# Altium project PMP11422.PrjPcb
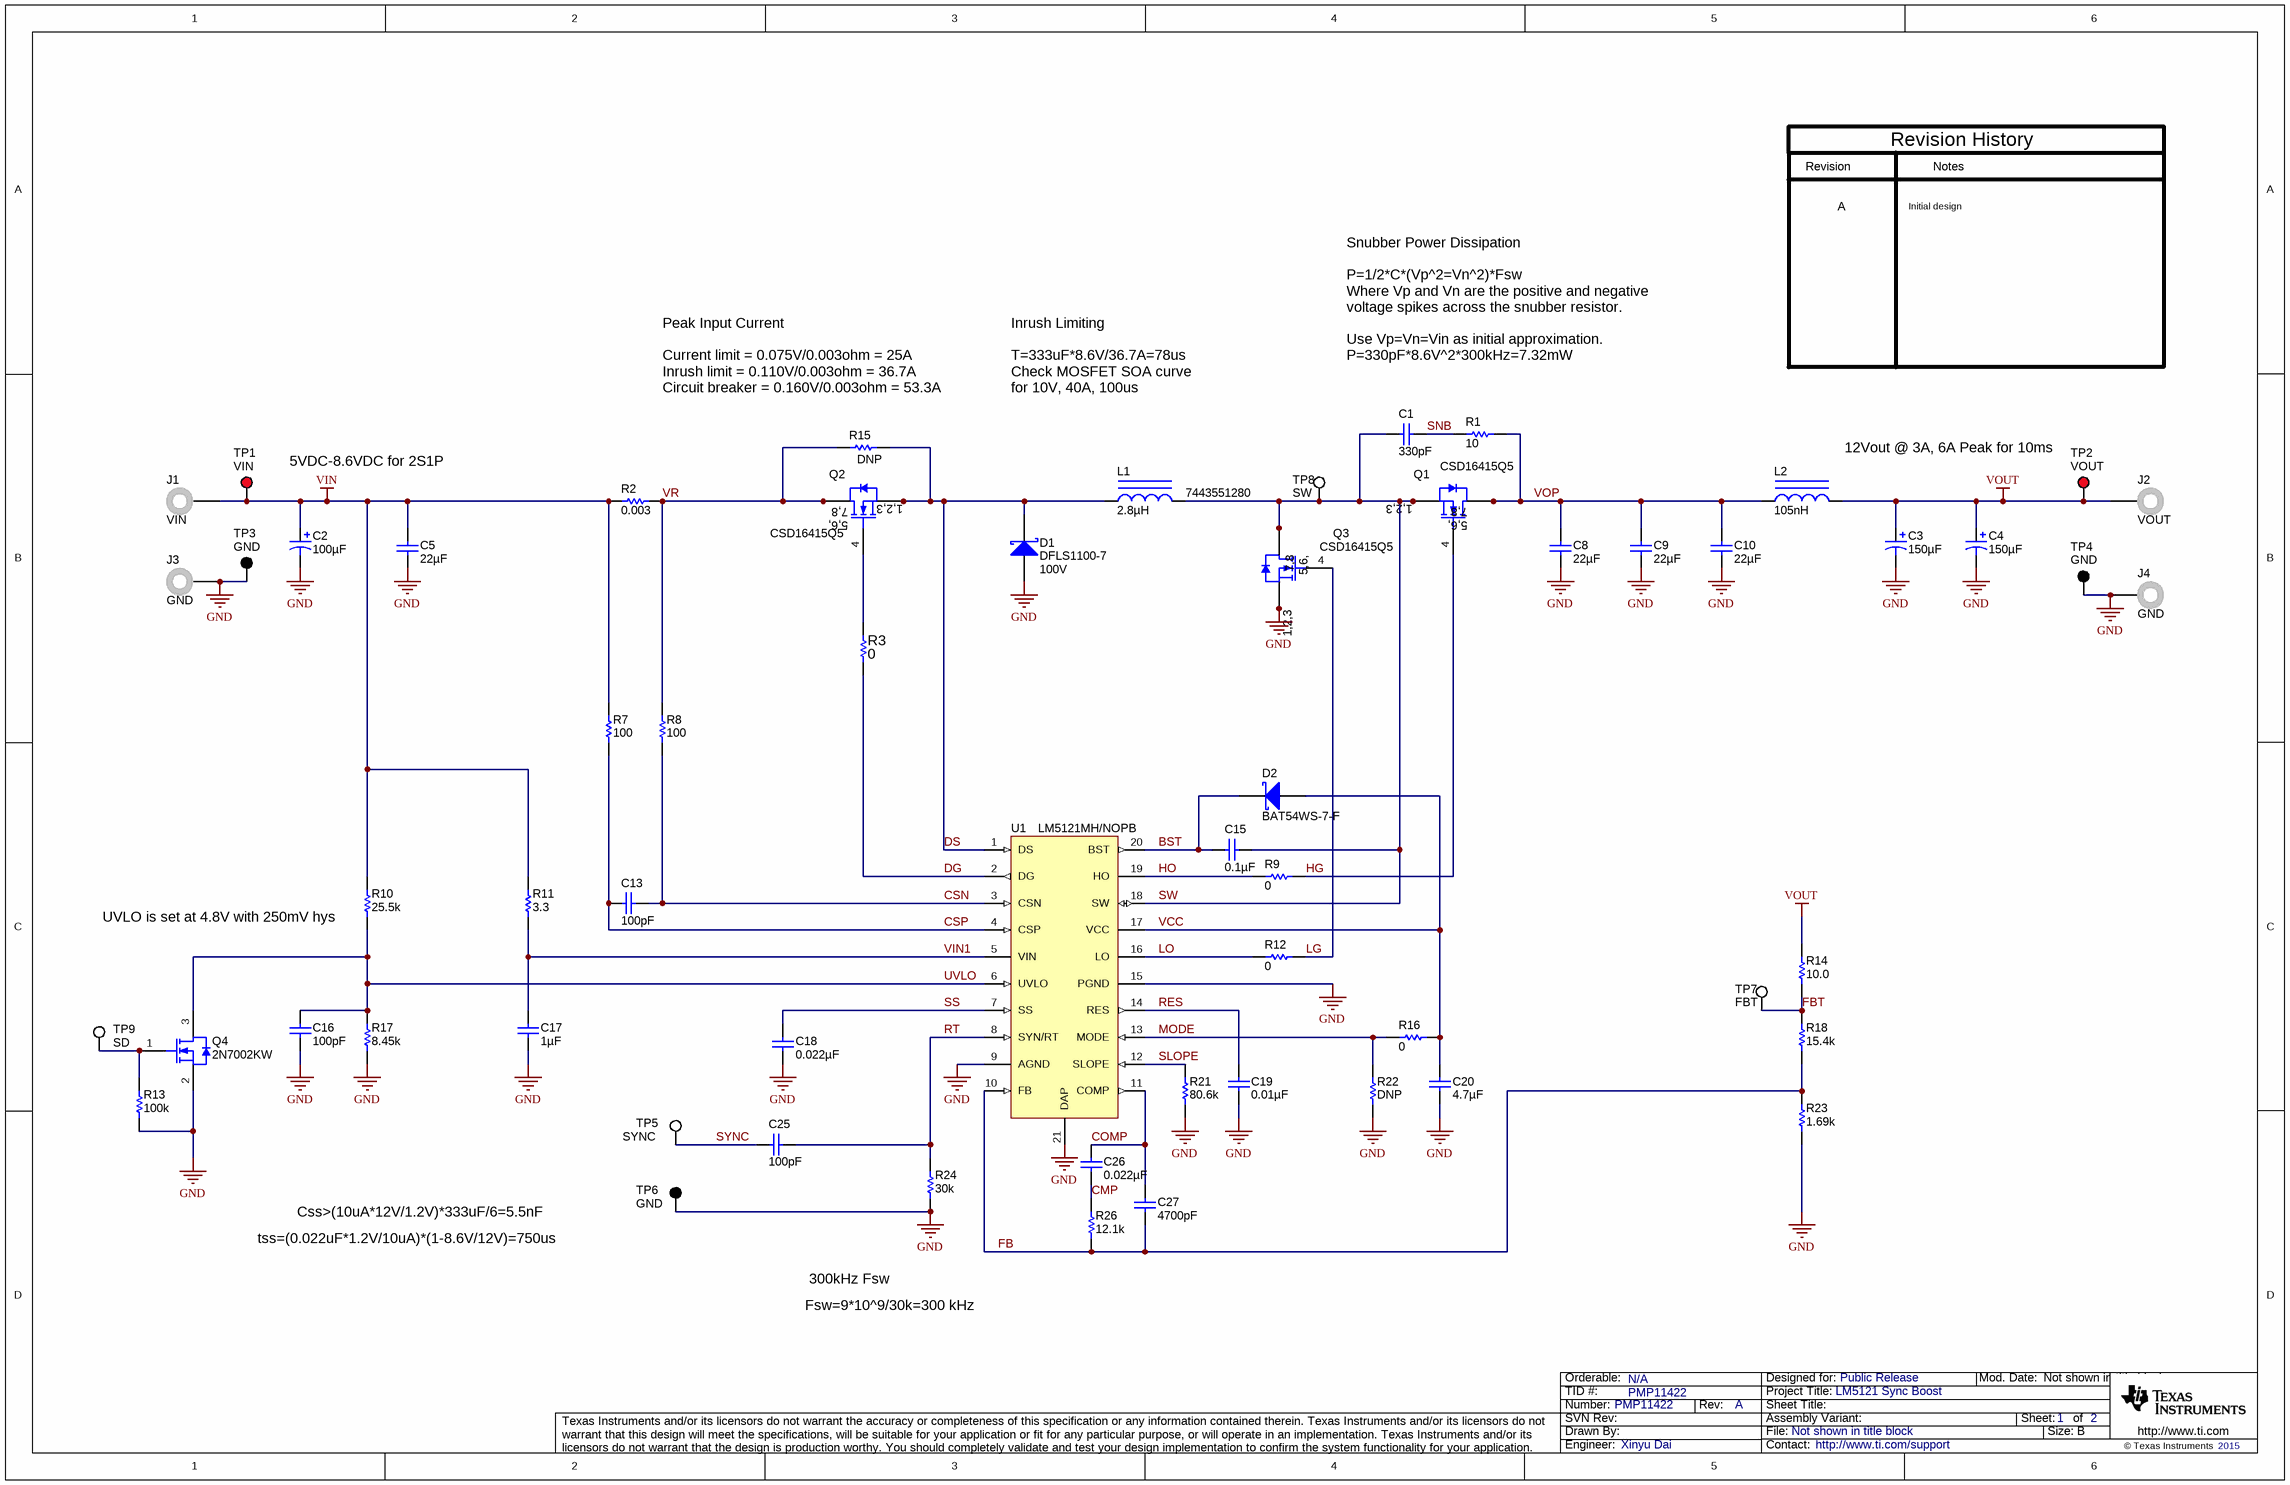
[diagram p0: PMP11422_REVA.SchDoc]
CopyrightYear: 2015; EVM_Orderable: N/A; PCB_Layout: Xinyu Dai; PCB_Rev: A; PRJ_Customer: Public Release; PRJ_Engineer: Xinyu Dai; PRJ_Number: PMP11422; PRJ_Title: LM5121 Sync Boost; SCH_Rev: A; TechSupport: http://www.ti.com/support; TID: PMP11422
2 sheets, 67 parts. Net scope: global (net labels, ports and power ports of the same name join across sheets).
Board file: PMP11422_REVA.PcbDoc
Sheets:
  PMP11422_REVA.SchDoc
  PMP11422_REVA_Hardware.SchDoc

## Sheet PMP11422_REVA.SchDoc
size 431 x 279 mm; Date: Not shown in title block; ApprovedBy: Not shown in title block; CheckedBy: Not shown in title block; Author: Not shown in title block; CompanyName: Not shown in title block; Engineer: Not shown in title block; Organization: Not shown in title block; Address1: Not shown in title block; Address2: Not shown in title block; Address3: Not shown in title block; Address4: Not shown in title block; DocumentNumber: 1; Revision: Use project parameter SCH_Rev; SheetNumber: 1; SheetTotal: 2; PageSetup: Record=PageOptions¦CenterHorizontal=True¦CenterVertical=True¦PrintScale=1.00¦XCorrection=1.00¦YCorrection=1.00¦PrintKind=0¦BorderSize=5000000¦LeftOffset=0¦BottomOffset=0¦Orientation=2¦PaperLength=1000¦PaperWidth=1000¦Scale=100¦PaperSource=15¦PrintQuality=600¦MediaType=1¦DitherType=10¦PaperKind=Letter¦PrintScaleMode=1

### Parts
C1  ValueDisplayed: 330pF  [0603]  (hidden comment: GRM188R72A331KA01D)
C2  ValueDisplayed: 100µF  [SM_RADIAL_D]  (hidden comment: EEE-FK1C101P)
C3  ValueDisplayed: 150µF  [MZJ_F80]  (hidden comment: EMZJ160ADA151MF80G)
C4  ValueDisplayed: 150µF  [MZJ_F80]  (hidden comment: EMZJ160ADA151MF80G)
C5  ValueDisplayed: 22µF  [1210]  (hidden comment: GRM32ER71E226KE15L)
C8  ValueDisplayed: 22µF  [1210]  (hidden comment: GRM32ER71E226KE15L)
C9  ValueDisplayed: 22µF  [1210]  (hidden comment: GRM32ER71E226KE15L)
C10  ValueDisplayed: 22µF  [1210]  (hidden comment: GRM32ER71E226KE15L)
C13  ValueDisplayed: 100pF  [0402]  (hidden comment: GRM1555C1H101JA01D)
C15  ValueDisplayed: 0.1µF  [0402]  (hidden comment: GRM155R71C104KA88D)
C16  ValueDisplayed: 100pF  [0402]  (hidden comment: GRM1555C1H101JA01D)
C17  ValueDisplayed: 1µF  [0603]  (hidden comment: GRM188R71C105KA12D)
C18  ValueDisplayed: 0.022µF  [0402]  (hidden comment: GCM155R71H223KA55D)
C19  ValueDisplayed: 0.01µF  [0402]  (hidden comment: GCM155R71H103KA55D)
C20  ValueDisplayed: 4.7µF  [0603]  (hidden comment: GRM188R61C475KAAJ)
C25  ValueDisplayed: 100pF  [0402]  (hidden comment: GRM1555C1H101JA01D)
C26  ValueDisplayed: 0.022µF  [0402]  (hidden comment: GCM155R71H223KA55D)
C27  ValueDisplayed: 4700pF  [0402]  (hidden comment: GRM155R71H472KA01D)
D1  DFLS1100-7  value 100V  [powerDI123]
D2  BAT54WS-7-F  [sod-323]
J1  VIN  [Keystone575-8]
J2  VOUT  [Keystone575-8]
J3  GND  [Keystone575-8]
J4  GND  [Keystone575-8]
L1  7443551280  ValueDisplayed: 2.8µH  [WE-HCA1]
L2  ValueDisplayed: 105nH  [WE-HCM_7050]  (hidden comment: 744302010)
Q1  CSD16415Q5  [TRANS_NexFET_Q5]
Q2  CSD16415Q5  [TRANS_NexFET_Q5]
Q3  CSD16415Q5  [TRANS_NexFET_Q5]
Q4  2N7002KW  [SOT-323]
R1  value 10  [1206]  (hidden comment: CRCW120610R0JNEA)
R2  ValueDisplayed: 0.003  [2512]  (hidden comment: ERJ-M1WSF3M0U)
R3  value 0  [0402]  (hidden comment: CRCW04020000Z0ED)
R7  ValueDisplayed: 100  [0402]  (hidden comment: CRCW0402100RJNED)
R8  ValueDisplayed: 100  [0402]  (hidden comment: CRCW0402100RJNED)
R9  value 0  [0402]  (hidden comment: CRCW04020000Z0ED)
R10  ValueDisplayed: 25.5k  [0402]  (hidden comment: CRCW040225K5FKED)
R11  value 3.3  [0402]  (hidden comment: CRCW04023R30JNED)
R12  value 0  [0402]  (hidden comment: CRCW04020000Z0ED)
R13  ValueDisplayed: 100k  [0402]  (hidden comment: CRCW0402100KJNED)
R14  value 10.0  [0402]  (hidden comment: CRCW040210R0FKED)
R15  DNP  [2512]
R16  value 0  [0402]  (hidden comment: CRCW04020000Z0ED)
R17  ValueDisplayed: 8.45k  [0402]  (hidden comment: CRCW04028K45FKED)
R18  ValueDisplayed: 15.4k  [0402]  (hidden comment: CRCW040215K4FKED)
R21  ValueDisplayed: 80.6k  [0402]  (hidden comment: CRCW040280K6FKED)
R22  value DNP  [0402]  (hidden comment: DNP1)
R23  value 1.69k  [0402]  (hidden comment: CRCW04021K69FKED)
R24  ValueDisplayed: 30k  [0402]  (hidden comment: CRCW040230K0JNED)
R26  ValueDisplayed: 12.1k  [0402]  (hidden comment: CRCW040212K1FKED)
TP1  VIN  [Keystone5010]
TP2  VOUT  [Keystone5010]
TP3  GND  [Keystone5011]
TP4  GND  [Keystone5011]
TP5  SYNC  [Keystone5012]
TP6  GND  [Keystone5011]
TP7  FBT  [Keystone5012]
TP8  SW  [Keystone5012]
TP9  SD  [Keystone5012]
U1  LM5121MH/NOPB  [PWP0020A_N]

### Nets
GND: C2.2(-) C3.2(-) C4.2(-) C5.2 C8.2 C9.2 C10.2 C16.2 C17.2 C18.2 C19.2 C20.2 D1.2(A) J3.1 J4.1 Q3.1(S) Q3.2(S) Q3.3(S) Q4.2(S) R13.1 R17.1 R21.1 R22.1 R23.1 R24.1 TP3.1 TP4.1 TP6.1 U1.9(AGND) U1.15(PGND) U1.21(DAP)
VIN: C2.1(+) C5.1 J1.1 R2.1 R7.2 R10.2 R11.2 TP1.1
VOUT: C3.1(+) C4.1(+) J2.1 L2.2 R14.2 TP2.1
BST: C15.1 D2.1(K) U1.20(BST)
CMP: C26.2 R26.2
COMP: C26.1 C27.2 U1.11(COMP)
CSN: C13.1 R8.1 U1.3(CSN)
CSP: C13.2 R7.1 U1.4(CSP)
DG: R3.2 U1.2(DG)
DS: D1.1(K) L1.1 Q2.1(S) Q2.2(S) Q2.3(S) R15.2 U1.1(DS)
FB: C27.1 R18.1 R23.2 R26.1 U1.10(FB)
FBT: R14.1 R18.2 TP7.1
HG: Q1.4(G) R9.2
HO: R9.1 U1.19(HO)
LG: Q3.4(G) R12.2
LO: R12.1 U1.16(LO)
MODE: R16.2 R22.2 U1.13(MODE)
RES: C19.1 U1.14(RES)
RT: C25.1 R24.2 U1.8(SYN/RT)
SLOPE: R21.2 U1.12(SLOPE)
SNB: C1.1 R1.1
SS: C18.1 U1.7(SS)
SW: C1.2 C15.2 L1.2 Q1.1(S) Q1.2(S) Q1.3(S) Q3.5(D) Q3.6(D) Q3.7(D) Q3.8(D) Q3.9(D) TP8.1 U1.18(SW)
SYNC: C25.2 TP5.1
UVLO: C16.1 Q4.3(D) R10.1 R17.2 U1.6(UVLO)
VCC: C20.1 D2.2(A) R16.1 U1.17(VCC)
VIN1: C17.1 R11.1 U1.5(VIN)
VOP: C8.1 C9.1 C10.1 L2.1 Q1.5(D) Q1.6(D) Q1.7(D) Q1.8(D) Q1.9(D) R1.2
VR: Q2.5(D) Q2.6(D) Q2.7(D) Q2.8(D) Q2.9(D) R2.2 R8.2 R15.1
NetQ2_4: Q2.4(G) R3.1
NetQ4_1: Q4.1(G) R13.2 TP9.1

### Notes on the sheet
- Revision
- Notes
- Revision History
- A
- Initial design
- Snubber Power Dissipation
  P=1/2*C*(Vp^2=Vn^2)*Fsw
  Where Vp and Vn are the positive and negative voltage spikes across the snubber resistor.
  Use Vp=Vn=Vin as initial approximation.
  P=330pF*8.6V^2*300kHz=7.32mW
- (near R15) Peak Input Current
  Current limit = 0.075V/0.003ohm = 25A
  Inrush limit = 0.110V/0.003ohm = 36.7A
  Circuit breaker = 0.160V/0.003ohm = 53.3A
- Inrush Limiting
  T=333uF*8.6V/36.7A=78us
  Check MOSFET SOA curve
  for 10V, 40A, 100us
- 5VDC-8.6VDC for 2S1P
- 12Vout @ 3A, 6A Peak for 10ms
- (near R10) UVLO is set at 4.8V with 250mV hys
- tss=(0.022uF*1.2V/10uA)*(1-8.6V/12V)=750us
- Css>(10uA*12V/1.2V)*333uF/6=5.5nF
- 300kHz Fsw
- Fsw=9*10^9/30k=300 kHz

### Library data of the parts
C1 = GRM188R72A331KA01D: CAP, CERM, 330pF, 100V, +/-10%, X7R, 0603; Manufacturer: MuRata; Polarized: N; CompType: Capacitor; U/M: EA; Cap_F: 0.00000000033; Tolerance_%: 10; Value1: Unknown; VDC_V: 100; TaMin_C: -55; TaMax_C: 125
C2 = EEE-FK1C101P: CAP, AL, 100 µF, 16 V, +/- 20%, 0.36 ohm, SMD; Manufacturer: Panasonic; Polarized: Y; CompType: Capacitor; Value: 100uF; U/M: EA; Cap_F: 0.0001; Tolerance_%: 20; VDC_V: 16; Value2: 16V; ESR_ohm: 0.36; IRMS_A: 0.24; TaMin_C: -55; TaMax_C: 105; Cap_Case: D; AEC Category: Q200
C3 C4 = EMZJ160ADA151MF80G: CAP, AL, 150 µF, 16 V, +/- 20%, 0.16 ohm, SMD; Manufacturer: Chemi-Con; Polarized: Y; CompType: Capacitor; Value: 150uF; U/M: EA; Cap_F: 0.00015; Tolerance_%: 20; VDC_V: 16; Value2: 16V; ESR_ohm: 0.16; IRMS_A: 0.6; TaMin_C: -55; TaMax_C: 105; Cap_Case: 6.3x7.7mm; AEC Category: Q200; AEC Qualified: N
C5 = GRM32ER71E226KE15L: CAP, CERM, 22 µF, 25 V, +/- 10%, X7R, 1210; Manufacturer: MuRata; Polarized: N; CompType: Capacitor; Value: 22uF; U/M: EA; Cap_F: 0.000022; Tolerance_%: 10; Value1: Unknown; VDC_V: 25; TaMin_C: -55; TaMax_C: 125; Value2: 25V; AEC Category: Q200
C8-C10 = GRM32ER71E226KE15L: CAP, CERM, 22 µF, 25 V, +/- 10%, X7R, 1210; Manufacturer: MuRata; Polarized: N; CompType: Capacitor; Value: 22uF; U/M: EA; Cap_F: 0.000022; Tolerance_%: 10; Value1: Unknown; VDC_V: 25; Value2: 25V; TaMin_C: -55; TaMax_C: 125; AEC Category: Q200
C13 = GRM1555C1H101JA01D: CAP, CERM, 100pF, 50V, +/-5%, C0G/NP0, 0402; Manufacturer: MuRata; Polarized: N; CompType: Capacitor; U/M: EA; Cap_F: 0.0000000001; Tolerance_%: 5; Value1: Unknown; VDC_V: 50; TaMin_C: -55; TaMax_C: 125
C15 = GRM155R71C104KA88D: CAP, CERM, 0.1uF, 16V, +/-10%, X7R, 0402; Manufacturer: MuRata; Polarized: N; CompType: Capacitor; U/M: EA; Cap_F: 0.0000001; Tolerance_%: 10; Value1: Unknown; VDC_V: 16; TaMin_C: -55; TaMax_C: 125
C16 C25 = GRM1555C1H101JA01D: CAP, CERM, 100 pF, 50 V, +/- 5%, C0G/NP0, 0402; Manufacturer: MuRata; Polarized: N; CompType: Capacitor; Value: 100pF; U/M: EA; Cap_F: 0.0000000001; Tolerance_%: 5; Value1: Unknown; VDC_V: 50; Value2: 50V; TaMin_C: -55; TaMax_C: 125; AEC Category: Q200
C17 = GRM188R71C105KA12D: CAP, CERM, 1 µF, 16 V, +/- 10%, X7R, 0603; Manufacturer: MuRata; Polarized: N; CompType: Capacitor; Value: 1uF; U/M: EA; Cap_F: 0.000001; Tolerance_%: 10; ESR_ohm: 0.011; Value1: 0.011 ohm; VDC_V: 16; Value2: 16V; TaMin_C: -55; TaMax_C: 125; AEC Category: Q200
C18 C26 = GCM155R71H223KA55D: CAP, CERM, 0.022 µF, 50 V, +/- 10%, C0G/NP0, 0402; Manufacturer: MuRata; Polarized: N; CompType: Capacitor; Value: 0.022uF; U/M: EA; Cap_F: 0.000000022; Tolerance_%: 10; Value1: Unknown; VDC_V: 50; Value2: 50V; TaMin_C: -55; TaMax_C: 125; AEC Category: Q200
C19 = GCM155R71H103KA55D: CAP, CERM, 0.01 µF, 50 V, +/- 10%, C0G/NP0, 0402; Manufacturer: MuRata; Polarized: N; CompType: Capacitor; Value: 0.01uF; U/M: EA; Cap_F: 0.00000001; Tolerance_%: 10; Value1: Unknown; VDC_V: 50; Value2: 50V; TaMin_C: -55; TaMax_C: 125; AEC Category: Q200
C20 = GRM188R61C475KAAJ: CAP, CERM, 4.7 µF, 16 V, +/- 10%, X5R, 0603; Manufacturer: MuRata; Polarized: N; CompType: Capacitor; Value: 4.7uF; U/M: EA; Cap_F: 0.0000047; Tolerance_%: 10; Value1: Unknown; VDC_V: 16; Value2: 16V; TaMin_C: -55; TaMax_C: 85; AEC Category: Q200
C27 = GRM155R71H472KA01D: CAP, CERM, 4700 pF, 50 V, +/- 10%, X7R, 0402; Manufacturer: MuRata; Polarized: N; CompType: Capacitor; Value: 4700pF; U/M: EA; Cap_F: 0.0000000047; Tolerance_%: 10; Value1: Unknown; VDC_V: 50; Value2: 50V; TaMin_C: -55; TaMax_C: 125; AEC Category: Q200
D1 = DFLS1100-7: Diode, Schottky, 100V, 1A, PowerDI123; Manufacturer: Diodes Inc.; U/M: EA; Vf_V: 0.77; Value2: 0.77V; Io_A: 1; Vr_V: 100; TJmax_C: 175; RJC_CperW: 7
D2 = BAT54WS-7-F: Diode, Schottky, 30 V, 0.2 A, SOD-323; Manufacturer: Diodes Inc.; Value: 30V; U/M: EA; Vf_V: 0.7; Value1: 0.2A; Value2: 0.7V; Io_A: 0.2; Vr_V: 30; TJmax_C: 125; AEC Category: Q101
J1-J4 = 575-8: Standard Banana Jack, Uninsulated, 8.9mm; Manufacturer: Keystone; CompType: Connector; U/M: EA
L1 = 7443551280: Inductor, Shielded Drum Core, WE-Perm, 2.8 µH, 17.5 A, 0.0033 ohm, SMD; Manufacturer: Wurth Elektronik; Value: 2.8uH; Ind_H: 2.8E-6; Imax_A: 17.5; Irms: 20A @ 50C rise; Isat: 17.5A @ 30% inductance drop; DCR_ohm: 0.0033; Value2: 17.5A; AEC Category: Q200
L2 = 744302010: Inductor, Shielded Drum Core, Ferrite, 105 nH, 30 A, 0.000235 ohm, SMD; Manufacturer: Wurth Elektronik; Value: 105nH; Ind_H: 105.0E-9; Imax_A: 30; Irms: 30A @ 50C rise; Isat: 45A @ 20% inductance drop; Value2: 30A; AEC Category: Q200
Q1 Q3 = CSD16415Q5: MOSFET, N-CH, 25 V, 100 A, SON 5x6mm; Manufacturer: Texas Instruments; Alternate Manufacturer: None; Value: 25V; U/M: EA; ChType: N; VdsMax_V: 25; Value1: 0.0015 ohm; Rdson45_ohm: 0.0015; Value2: 21 nC; QgTyp_nC: 21; Vgs_V: 16; IdsMax_A: 100; AEC Category: Q101
Q2 = CSD16415q5: MOSFET, N-CH, 25 V, 100 A, SON 5x6mm; Manufacturer: Texas Instruments; Alternate Manufacturer: None; Value: 25V; U/M: EA; ChType: N; VdsMax_V: 25; Value1: 0.0015 ohm; Rdson45_ohm: 0.0015; Value2: 21 nC; QgTyp_nC: 21; Vgs_V: 16; IdsMax_A: 100; AEC Category: Q101
Q4 = 2N7002KW: MOSFET, N-CH, 60 V, 0.31 A, SOT-323; Manufacturer: Fairchild Semiconductor; Alternate Manufacturer: None; U/M: EA; ChType: N; Value: 60V; VdsMax_V: 60; Value1: 1.6 ohm; Rdson45_ohm: 1.6; Value2: ? nC; Vgs_V: 2.1; IdsMax_A: 0.31; AEC Category: Q101
R1 = CRCW120610R0JNEA: RES, 10 ohm, 5%, 0.25W, 1206; Manufacturer: Vishay-Dale; CompType: Resistor; Value_Code: 10R0; Tolerance_%: 5; Power_W: 0.25; VDC_V: 200; TempCo: 200 ppm/C; EIA_Code: E24; U/M: EA
R2 = ERJ-M1WSF3M0U: RES, 0.003, 1%, 1 W, 2512; Manufacturer: Panasonic; CompType: Resistor; Value: 0.003; Value_Code: 3L000; Tolerance_%: 1; Value2: 1W; TempCo: 350 ppm/C; EIA_Code: E96; U/M: EA; AEC Category: Q200
R3 = CRCW04020000Z0ED: RES, 0 ohm, 5%, 0.063W, 0402; Manufacturer: Vishay-Dale; CompType: Resistor; U/M: EA; Value_Code: 0000; Tolerance_%: 5; Power_W: 0.063; VDC_V: 50; TempCo: 200 ppm/C; EIA_Code: E24
R7 R8 = CRCW0402100RJNED: RES, 100, 5%, 0.063 W, 0402; Manufacturer: Vishay-Dale; CompType: Resistor; Value: 100; Value_Code: 100R; Tolerance_%: 5; Power_W: 0.063; Value2: 0.063W; VDC_V: 50; TempCo: 200 ppm/C; EIA_Code: E24; U/M: EA; AEC Category: Q200
R9 R12 R16 = CRCW04020000Z0ED: RES, 0 ohm, 5%, 0.063W, 0402; Manufacturer: Vishay-Dale; CompType: Resistor; Value_Code: 0000; Tolerance_%: 5; Power_W: 0.063; VDC_V: 50; TempCo: 200 ppm/C; EIA_Code: E24; U/M: EA
R10 = CRCW040225K5FKED: RES, 25.5 k, 1%, 0.063 W, 0402; Manufacturer: Vishay-Dale; CompType: Resistor; Value: 25.5k; Res_ohm: 25500; Value_Code: 25k5; Tolerance_%: 1; Power_W: 0.063; Value2: 0.063W; VDC_V: 50; TempCo: 100 ppm/C; EIA_Code: E96; U/M: EA; AEC Category: Q200
R11 = CRCW04023R30JNED: RES, 3.3 ohm, 5%, 0.063W, 0402; Manufacturer: Vishay-Dale; CompType: Resistor; Value_Code: 3R30; Tolerance_%: 5; Power_W: 0.063; VDC_V: 50; TempCo: 200 ppm/C; EIA_Code: E24; U/M: EA
R13 = CRCW0402100KJNED: RES, 100 k, 5%, 0.063 W, 0402; Manufacturer: Vishay-Dale; CompType: Resistor; Value: 100k; Res_ohm: 100000; Tolerance_%: 5; Power_W: 0.063; Value2: 0.063W; VDC_V: 50; TempCo: 200 ppm/C; EIA_Code: E24; U/M: EA; AEC Category: Q200
R14 = CRCW040210R0FKED: RES, 10.0 ohm, 1%, 0.063W, 0402; Manufacturer: Vishay-Dale; CompType: Resistor; Res_ohm: 10; Value_Code: 10R0; Tolerance_%: 1; Power_W: 0.063; VDC_V: 50; TempCo: 100 ppm/C; EIA_Code: E96; U/M: EA
R15 = ERJ-M1WTF1M0U: RES, 0.001, 1%, 1 W, 2512; Manufacturer: Panasonic; CompType: Resistor; Value: 0.001; Value_Code: 1L000; Tolerance_%: 1; Value2: 1W; TempCo: ppm/C; EIA_Code: E96; U/M: EA; AEC Category: Q200
R17 = CRCW04028K45FKED: RES, 8.45 k, 1%, 0.063 W, 0402; Manufacturer: Vishay-Dale; CompType: Resistor; Value: 8.45k; Res_ohm: 8450; Value_Code: 8k45; Tolerance_%: 1; Power_W: 0.063; Value2: 0.063W; VDC_V: 50; TempCo: 100 ppm/C; EIA_Code: E96; U/M: EA; AEC Category: Q200
R18 = CRCW040215K4FKED: RES, 15.4 k, 1%, 0.063 W, 0402; Manufacturer: Vishay-Dale; CompType: Resistor; Value: 15.4k; Res_ohm: 15400; Value_Code: 15k4; Tolerance_%: 1; Power_W: 0.063; Value2: 0.063W; VDC_V: 50; TempCo: 100 ppm/C; EIA_Code: E96; U/M: EA; AEC Category: Q200
R21 = CRCW040280K6FKED: RES, 80.6 k, 1%, 0.063 W, 0402; Manufacturer: Vishay-Dale; CompType: Resistor; Value: 80.6k; Res_ohm: 80600; Value_Code: 80k6; Tolerance_%: 1; Power_W: 0.063; Value2: 0.063W; VDC_V: 50; TempCo: 100 ppm/C; EIA_Code: E96; U/M: EA; AEC Category: Q200
R22 = Resistor: RES, xxx ohm, x%, xW, [PackageReference]; Manufacturer: Used in BOM report; U/M: EA
R23 = CRCW04021K69FKED: RES, 1.69k ohm, 1%, 0.063W, 0402; Manufacturer: Vishay-Dale; CompType: Resistor; Res_ohm: 1690; Value_Code: 1k69; Tolerance_%: 1; Power_W: 0.063; VDC_V: 50; TempCo: 100 ppm/C; EIA_Code: E96; U/M: EA
R24 = CRCW040230K0JNED: RES, 30 k, 5%, 0.063 W, 0402; Manufacturer: Vishay-Dale; CompType: Resistor; Value: 30k; Res_ohm: 30000; Value_Code: 30k0; Tolerance_%: 5; Power_W: 0.063; Value2: 0.063W; VDC_V: 50; TempCo: 200 ppm/C; EIA_Code: E24; U/M: EA; AEC Category: Q200
R26 = CRCW040212K1FKED: RES, 12.1 k, 1%, 0.063 W, 0402; Manufacturer: Vishay-Dale; CompType: Resistor; Value: 12.1k; Res_ohm: 12100; Value_Code: 12k1; Tolerance_%: 1; Power_W: 0.063; Value2: 0.063W; VDC_V: 50; TempCo: 100 ppm/C; EIA_Code: E96; U/M: EA; AEC Category: Q200
TP1 TP2 = 5010: Test Point, Multipurpose, Red, TH; Manufacturer: Keystone; CompType: Test Point Loop; U/M: EA
TP3 TP4 TP6 = 5011: Test Point, Multipurpose, Black, TH; Manufacturer: Keystone; CompType: Test Point Loop; U/M: EA
TP5 TP7-TP9 = 5012: Test Point, Multipurpose, White, TH; Manufacturer: Keystone; CompType: Test Point Loop; U/M: EA
U1 = LM5121MH/NOPB: Wide Input Synchronous Boost Controller with Disconnection Switch Control, PWP0020A; Alternate Manufacturer: None; Manufacturer: Texas Instruments; SymbolCreator: a0411947; CompType: IC; U/M: EA

## Sheet PMP11422_REVA_Hardware.SchDoc
size 431 x 279 mm; Date: Not shown in title block; ApprovedBy: Not shown in title block; CheckedBy: Not shown in title block; Author: Not shown in title block; CompanyName: Not shown in title block; Engineer: Not shown in title block; Organization: Not shown in title block; Address1: Not shown in title block; Address2: Not shown in title block; Address3: Not shown in title block; Address4: Not shown in title block; DocumentNumber: 2; Revision: Use project parameter SCH_Rev; SheetNumber: 2; SheetTotal: 2; PageSetup: Record=PageOptions¦CenterHorizontal=True¦CenterVertical=True¦PrintScale=1.00¦XCorrection=1.00¦YCorrection=1.00¦PrintKind=0¦BorderSize=5000000¦LeftOffset=0¦BottomOffset=0¦Orientation=2¦PaperLength=1000¦PaperWidth=1000¦Scale=100¦PaperSource=15¦PrintQuality=600¦MediaType=1¦DitherType=10¦PaperKind=Letter¦PrintScaleMode=1
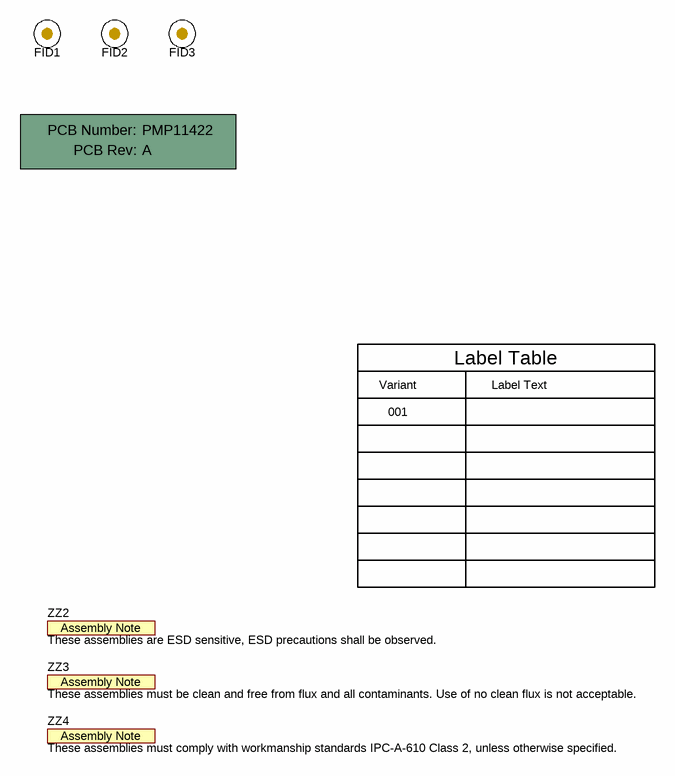
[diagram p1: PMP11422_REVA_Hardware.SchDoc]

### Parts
!PCB  Printed Circuit Board  (value not drawn)  (mechanical)
FID1  Fiducial  [Fiducial10-20]  (value not drawn)
FID2  Fiducial  [Fiducial10-20]  (value not drawn)
FID3  Fiducial  [Fiducial10-20]  (value not drawn)
ZZ2  These assemblies are ESD sensitive, ESD precautions shall be observed.  [AssemblyNote]  (no BOM)
ZZ3  These assemblies must be clean and free from flux and all contaminants. Use of no clean flux is not acceptable.  [AssemblyNote]  (no BOM)
ZZ4  These assemblies must comply with workmanship standards IPC-A-610 Class 2, unless otherwise specified.  [AssemblyNote]  (no BOM)

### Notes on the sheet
- Variant
- Label Table
- Label Text
- 001

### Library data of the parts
!PCB = PCB: Manufacturer: Any; PartNumber: PMP11422; SymbolCreator: a0412235
FID1-FID3 = Fiducial: Fiducial mark.  There is nothing to buy or mount.; SymbolCreator: codlsc
ZZ2-ZZ4 = AssemblyNote: SymbolCreator: codlsc

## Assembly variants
001: not fitted FID1 FID2 FID3 R15 R22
